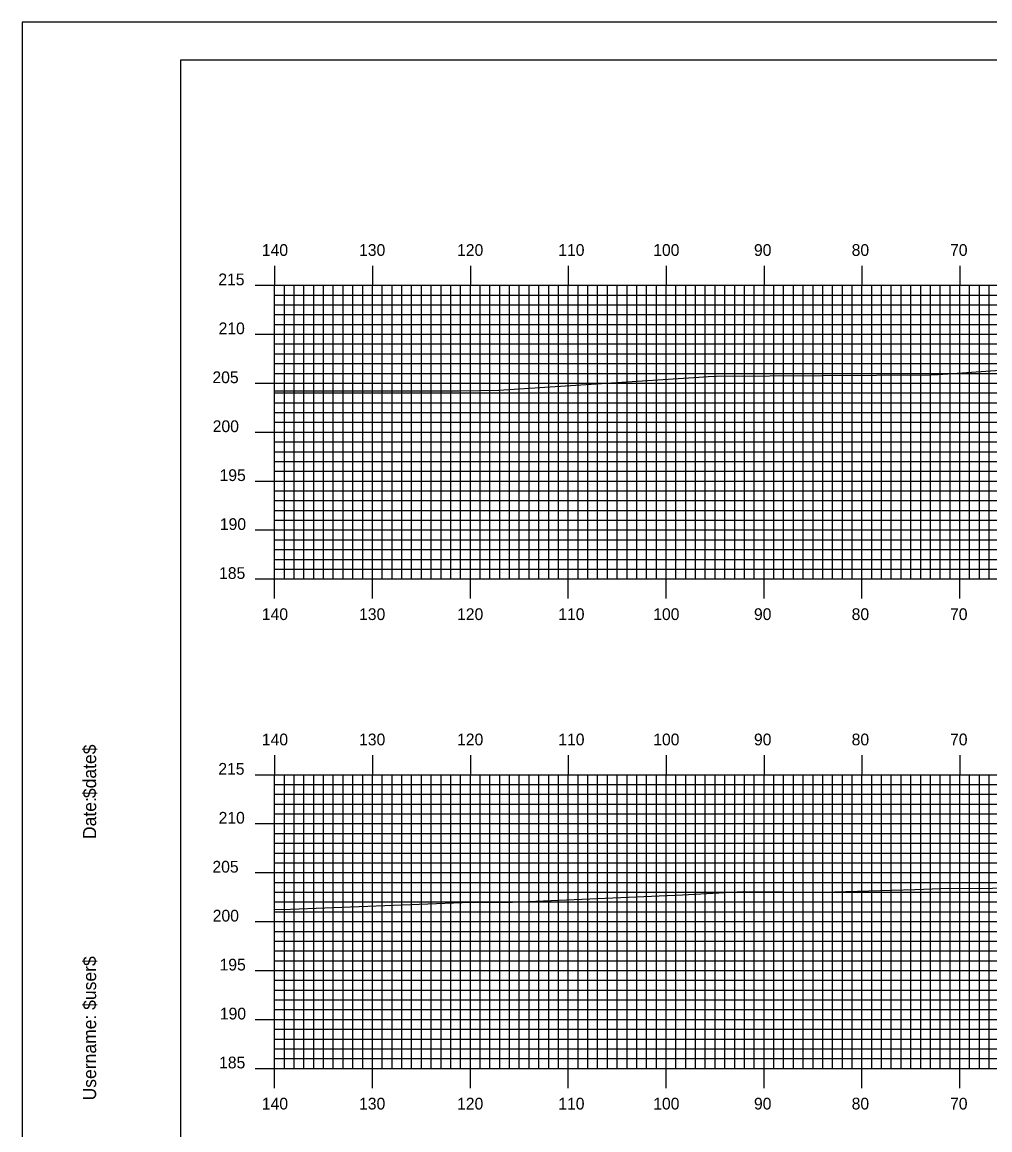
# Model space of a CAD drawing. Extents: x 1799568 to 1799912, y 442591 to 442811.
# Drawn here: x 1799568.2 to 1799667.1, y 442697.4 to 442810.5 of the extents above; entities that cross this region are included whole.
import ezdxf

# ---------------------------------------------------------------- set-up
doc = ezdxf.new("R2010")
doc.units = 0
for name, color, linetype in [('BORDER', 7, 'Continuous'), ('H_V ANNOTATION', 7, 'Continuous'), ('MAJOR', 7, 'Continuous'), ('MINOR', 7, 'Continuous'), ('PLOT BOUNDARY', 7, 'Continuous'), ('S_Roadway_Centerline', 7, 'Continuous')]:
    doc.layers.add(name, color=color, linetype=linetype)

msp = doc.modelspace()

# ---------------------------------------------------------------- linework, layer by layer
at = {"layer": 'BORDER'}
msp.add_lwpolyline([(1799584.41, 442596.67), (1799904.41, 442596.67), (1799904.41, 442806.67), (1799584.41, 442806.67)], close=True, dxfattribs=at)
at = {"layer": 'MAJOR'}
for p, q in [((1799594.01, 442785.67), (1799594.01, 442783.67)), ((1799604.01, 442785.67), (1799604.01, 442783.67)), ((1799614.01, 442785.67), (1799614.01, 442783.67)), ((1799624.01, 442785.67), (1799624.01, 442783.67)), ((1799634.01, 442785.67), (1799634.01, 442783.67)), ((1799644.01, 442785.67), (1799644.01, 442783.67)), ((1799654.01, 442785.67), (1799654.01, 442783.67)), ((1799664.01, 442785.67), (1799664.01, 442783.67)), ((1799592.01, 442783.67), (1799594.01, 442783.67)), ((1799594.01, 442783.67), (1799874.01, 442783.67)), ((1799594.01, 442753.67), (1799594.01, 442783.67)), ((1799594.01, 442753.67), (1799594.01, 442783.67)), ((1799594.01, 442783.67), (1799874.01, 442783.67)), ((1799604.01, 442753.67), (1799604.01, 442783.67)), ((1799614.01, 442753.67), (1799614.01, 442783.67)), ((1799624.01, 442753.67), (1799624.01, 442783.67)), ((1799634.01, 442753.67), (1799634.01, 442783.67)), ((1799644.01, 442753.67), (1799644.01, 442783.67)), ((1799654.01, 442753.67), (1799654.01, 442783.67)), ((1799664.01, 442753.67), (1799664.01, 442783.67)), ((1799592.01, 442778.67), (1799594.01, 442778.67)), ((1799594.01, 442778.67), (1799874.01, 442778.67)), ((1799592.01, 442773.67), (1799594.01, 442773.67)), ((1799594.01, 442773.67), (1799874.01, 442773.67)), ((1799592.01, 442768.67), (1799594.01, 442768.67)), ((1799594.01, 442768.67), (1799874.01, 442768.67)), ((1799592.01, 442763.67), (1799594.01, 442763.67)), ((1799594.01, 442763.67), (1799874.01, 442763.67)), ((1799592.01, 442758.67), (1799594.01, 442758.67)), ((1799594.01, 442758.67), (1799874.01, 442758.67)), ((1799592.01, 442753.67), (1799594.01, 442753.67)), ((1799594.01, 442753.67), (1799874.01, 442753.67)), ((1799594.01, 442753.67), (1799874.01, 442753.67)), ((1799594.01, 442751.66), (1799594.01, 442753.67)), ((1799604.01, 442751.66), (1799604.01, 442753.67)), ((1799614.01, 442751.66), (1799614.01, 442753.67)), ((1799624.01, 442751.66), (1799624.01, 442753.67)), ((1799634.01, 442751.66), (1799634.01, 442753.67)), ((1799644.01, 442751.66), (1799644.01, 442753.67)), ((1799654.01, 442751.66), (1799654.01, 442753.67)), ((1799664.01, 442751.66), (1799664.01, 442753.67)), ((1799594.01, 442735.67), (1799594.01, 442733.67)), ((1799604.01, 442735.67), (1799604.01, 442733.67)), ((1799614.01, 442735.67), (1799614.01, 442733.67)), ((1799624.01, 442735.67), (1799624.01, 442733.67)), ((1799634.01, 442735.67), (1799634.01, 442733.67)), ((1799644.01, 442735.67), (1799644.01, 442733.67)), ((1799654.01, 442735.67), (1799654.01, 442733.67)), ((1799664.01, 442735.67), (1799664.01, 442733.67)), ((1799592.01, 442733.67), (1799594.01, 442733.67)), ((1799594.01, 442733.67), (1799874.01, 442733.67)), ((1799594.01, 442703.67), (1799594.01, 442733.67)), ((1799594.01, 442703.67), (1799594.01, 442733.67)), ((1799594.01, 442733.67), (1799874.01, 442733.67)), ((1799604.01, 442703.67), (1799604.01, 442733.67)), ((1799614.01, 442703.67), (1799614.01, 442733.67)), ((1799624.01, 442703.67), (1799624.01, 442733.67)), ((1799634.01, 442703.67), (1799634.01, 442733.67)), ((1799644.01, 442703.67), (1799644.01, 442733.67)), ((1799654.01, 442703.67), (1799654.01, 442733.67)), ((1799664.01, 442703.67), (1799664.01, 442733.67)), ((1799592.01, 442728.67), (1799594.01, 442728.67)), ((1799594.01, 442728.67), (1799874.01, 442728.67)), ((1799592.01, 442723.67), (1799594.01, 442723.67)), ((1799594.01, 442723.67), (1799874.01, 442723.67)), ((1799592.01, 442718.67), (1799594.01, 442718.67)), ((1799594.01, 442718.67), (1799874.01, 442718.67)), ((1799592.01, 442713.67), (1799594.01, 442713.67)), ((1799594.01, 442713.67), (1799874.01, 442713.67)), ((1799592.01, 442708.67), (1799594.01, 442708.67)), ((1799594.01, 442708.67), (1799874.01, 442708.67)), ((1799592.01, 442703.67), (1799594.01, 442703.67)), ((1799594.01, 442703.67), (1799874.01, 442703.67)), ((1799594.01, 442703.67), (1799874.01, 442703.67)), ((1799594.01, 442701.66), (1799594.01, 442703.67)), ((1799604.01, 442701.66), (1799604.01, 442703.67)), ((1799614.01, 442701.66), (1799614.01, 442703.67)), ((1799624.01, 442701.66), (1799624.01, 442703.67)), ((1799634.01, 442701.66), (1799634.01, 442703.67)), ((1799644.01, 442701.66), (1799644.01, 442703.67)), ((1799654.01, 442701.66), (1799654.01, 442703.67)), ((1799664.01, 442701.66), (1799664.01, 442703.67))]:
    msp.add_line(p, q, dxfattribs=at)
at = {"layer": 'MINOR'}
for p, q in [((1799595.01, 442753.67), (1799595.01, 442783.67)), ((1799596.01, 442753.67), (1799596.01, 442783.67)), ((1799597.01, 442753.67), (1799597.01, 442783.67)), ((1799598.01, 442753.67), (1799598.01, 442783.67)), ((1799599.01, 442753.67), (1799599.01, 442783.67)), ((1799600.01, 442753.67), (1799600.01, 442783.67)), ((1799601.01, 442753.67), (1799601.01, 442783.67)), ((1799602.01, 442753.67), (1799602.01, 442783.67)), ((1799603.01, 442753.67), (1799603.01, 442783.67)), ((1799605.01, 442753.67), (1799605.01, 442783.67)), ((1799606.01, 442753.67), (1799606.01, 442783.67)), ((1799607.01, 442753.67), (1799607.01, 442783.67)), ((1799608.01, 442753.67), (1799608.01, 442783.67)), ((1799609.01, 442753.67), (1799609.01, 442783.67)), ((1799610.01, 442753.67), (1799610.01, 442783.67)), ((1799611.01, 442753.67), (1799611.01, 442783.67)), ((1799612.01, 442753.67), (1799612.01, 442783.67)), ((1799613.01, 442753.67), (1799613.01, 442783.67)), ((1799615.01, 442753.67), (1799615.01, 442783.67)), ((1799616.01, 442753.67), (1799616.01, 442783.67)), ((1799617.01, 442753.67), (1799617.01, 442783.67)), ((1799618.01, 442753.67), (1799618.01, 442783.67)), ((1799619.01, 442753.67), (1799619.01, 442783.67)), ((1799620.01, 442753.67), (1799620.01, 442783.67)), ((1799621.01, 442753.67), (1799621.01, 442783.67)), ((1799622.01, 442753.67), (1799622.01, 442783.67)), ((1799623.01, 442753.67), (1799623.01, 442783.67)), ((1799625.01, 442753.67), (1799625.01, 442783.67)), ((1799626.01, 442753.67), (1799626.01, 442783.67)), ((1799627.01, 442753.67), (1799627.01, 442783.67)), ((1799628.01, 442753.67), (1799628.01, 442783.67)), ((1799629.01, 442753.67), (1799629.01, 442783.67)), ((1799630.01, 442753.67), (1799630.01, 442783.67)), ((1799631.01, 442753.67), (1799631.01, 442783.67)), ((1799632.01, 442753.67), (1799632.01, 442783.67)), ((1799633.01, 442753.67), (1799633.01, 442783.67)), ((1799635.01, 442753.67), (1799635.01, 442783.67)), ((1799636.01, 442753.67), (1799636.01, 442783.67)), ((1799637.01, 442753.67), (1799637.01, 442783.67)), ((1799638.01, 442753.67), (1799638.01, 442783.67)), ((1799639.01, 442753.67), (1799639.01, 442783.67)), ((1799640.01, 442753.67), (1799640.01, 442783.67)), ((1799641.01, 442753.67), (1799641.01, 442783.67)), ((1799642.01, 442753.67), (1799642.01, 442783.67)), ((1799643.01, 442753.67), (1799643.01, 442783.67)), ((1799645.01, 442753.67), (1799645.01, 442783.67)), ((1799646.01, 442753.67), (1799646.01, 442783.67)), ((1799647.01, 442753.67), (1799647.01, 442783.67)), ((1799648.01, 442753.67), (1799648.01, 442783.67)), ((1799649.01, 442753.67), (1799649.01, 442783.67)), ((1799650.01, 442753.67), (1799650.01, 442783.67)), ((1799651.01, 442753.67), (1799651.01, 442783.67)), ((1799652.01, 442753.67), (1799652.01, 442783.67)), ((1799653.01, 442753.67), (1799653.01, 442783.67)), ((1799655.01, 442753.67), (1799655.01, 442783.67)), ((1799656.01, 442753.67), (1799656.01, 442783.67)), ((1799657.01, 442753.67), (1799657.01, 442783.67)), ((1799658.01, 442753.67), (1799658.01, 442783.67)), ((1799659.01, 442753.67), (1799659.01, 442783.67)), ((1799660.01, 442753.67), (1799660.01, 442783.67)), ((1799661.01, 442753.67), (1799661.01, 442783.67)), ((1799662.01, 442753.67), (1799662.01, 442783.67)), ((1799663.01, 442753.67), (1799663.01, 442783.67)), ((1799665.01, 442753.67), (1799665.01, 442783.67)), ((1799666.01, 442753.67), (1799666.01, 442783.67)), ((1799667.01, 442753.67), (1799667.01, 442783.67)), ((1799594.01, 442782.67), (1799874.01, 442782.67)), ((1799594.01, 442782.67), (1799596.01, 442782.67)), ((1799594.01, 442781.67), (1799874.01, 442781.67)), ((1799594.01, 442781.67), (1799596.01, 442781.67)), ((1799594.01, 442780.67), (1799874.01, 442780.67)), ((1799594.01, 442780.67), (1799596.01, 442780.67)), ((1799594.01, 442779.67), (1799874.01, 442779.67)), ((1799594.01, 442779.67), (1799596.01, 442779.67)), ((1799594.01, 442777.67), (1799874.01, 442777.67)), ((1799594.01, 442777.67), (1799596.01, 442777.67)), ((1799594.01, 442776.67), (1799874.01, 442776.67)), ((1799594.01, 442776.67), (1799596.01, 442776.67)), ((1799594.01, 442775.67), (1799874.01, 442775.67)), ((1799594.01, 442775.67), (1799596.01, 442775.67)), ((1799594.01, 442774.67), (1799874.01, 442774.67)), ((1799594.01, 442774.67), (1799596.01, 442774.67)), ((1799594.01, 442772.67), (1799874.01, 442772.67)), ((1799594.01, 442772.67), (1799596.01, 442772.67)), ((1799594.01, 442771.67), (1799874.01, 442771.67)), ((1799594.01, 442771.67), (1799596.01, 442771.67)), ((1799594.01, 442770.67), (1799874.01, 442770.67)), ((1799594.01, 442770.67), (1799596.01, 442770.67)), ((1799594.01, 442769.67), (1799874.01, 442769.67)), ((1799594.01, 442769.67), (1799596.01, 442769.67)), ((1799594.01, 442767.67), (1799874.01, 442767.67)), ((1799594.01, 442767.67), (1799596.01, 442767.67)), ((1799594.01, 442766.67), (1799874.01, 442766.67)), ((1799594.01, 442766.67), (1799596.01, 442766.67)), ((1799594.01, 442765.67), (1799874.01, 442765.67)), ((1799594.01, 442765.67), (1799596.01, 442765.67)), ((1799594.01, 442764.67), (1799874.01, 442764.67)), ((1799594.01, 442764.67), (1799596.01, 442764.67)), ((1799594.01, 442762.67), (1799874.01, 442762.67)), ((1799594.01, 442762.67), (1799596.01, 442762.67)), ((1799594.01, 442761.67), (1799874.01, 442761.67)), ((1799594.01, 442761.67), (1799596.01, 442761.67)), ((1799594.01, 442760.67), (1799874.01, 442760.67)), ((1799594.01, 442760.67), (1799596.01, 442760.67)), ((1799594.01, 442759.67), (1799874.01, 442759.67)), ((1799594.01, 442759.67), (1799596.01, 442759.67)), ((1799594.01, 442757.67), (1799874.01, 442757.67)), ((1799594.01, 442757.67), (1799596.01, 442757.67)), ((1799594.01, 442756.67), (1799874.01, 442756.67)), ((1799594.01, 442756.67), (1799596.01, 442756.67)), ((1799594.01, 442755.67), (1799874.01, 442755.67)), ((1799594.01, 442755.67), (1799596.01, 442755.67)), ((1799594.01, 442754.67), (1799874.01, 442754.67)), ((1799594.01, 442754.67), (1799596.01, 442754.67)), ((1799595.01, 442703.67), (1799595.01, 442733.67)), ((1799596.01, 442703.67), (1799596.01, 442733.67)), ((1799597.01, 442703.67), (1799597.01, 442733.67)), ((1799598.01, 442703.67), (1799598.01, 442733.67)), ((1799599.01, 442703.67), (1799599.01, 442733.67)), ((1799600.01, 442703.67), (1799600.01, 442733.67)), ((1799601.01, 442703.67), (1799601.01, 442733.67)), ((1799602.01, 442703.67), (1799602.01, 442733.67)), ((1799603.01, 442703.67), (1799603.01, 442733.67)), ((1799605.01, 442703.67), (1799605.01, 442733.67)), ((1799606.01, 442703.67), (1799606.01, 442733.67)), ((1799607.01, 442703.67), (1799607.01, 442733.67)), ((1799608.01, 442703.67), (1799608.01, 442733.67)), ((1799609.01, 442703.67), (1799609.01, 442733.67)), ((1799610.01, 442703.67), (1799610.01, 442733.67)), ((1799611.01, 442703.67), (1799611.01, 442733.67)), ((1799612.01, 442703.67), (1799612.01, 442733.67)), ((1799613.01, 442703.67), (1799613.01, 442733.67)), ((1799615.01, 442703.67), (1799615.01, 442733.67)), ((1799616.01, 442703.67), (1799616.01, 442733.67)), ((1799617.01, 442703.67), (1799617.01, 442733.67)), ((1799618.01, 442703.67), (1799618.01, 442733.67)), ((1799619.01, 442703.67), (1799619.01, 442733.67)), ((1799620.01, 442703.67), (1799620.01, 442733.67)), ((1799621.01, 442703.67), (1799621.01, 442733.67)), ((1799622.01, 442703.67), (1799622.01, 442733.67)), ((1799623.01, 442703.67), (1799623.01, 442733.67)), ((1799625.01, 442703.67), (1799625.01, 442733.67)), ((1799626.01, 442703.67), (1799626.01, 442733.67)), ((1799627.01, 442703.67), (1799627.01, 442733.67)), ((1799628.01, 442703.67), (1799628.01, 442733.67)), ((1799629.01, 442703.67), (1799629.01, 442733.67)), ((1799630.01, 442703.67), (1799630.01, 442733.67)), ((1799631.01, 442703.67), (1799631.01, 442733.67)), ((1799632.01, 442703.67), (1799632.01, 442733.67)), ((1799633.01, 442703.67), (1799633.01, 442733.67)), ((1799635.01, 442703.67), (1799635.01, 442733.67)), ((1799636.01, 442703.67), (1799636.01, 442733.67)), ((1799637.01, 442703.67), (1799637.01, 442733.67)), ((1799638.01, 442703.67), (1799638.01, 442733.67)), ((1799639.01, 442703.67), (1799639.01, 442733.67)), ((1799640.01, 442703.67), (1799640.01, 442733.67)), ((1799641.01, 442703.67), (1799641.01, 442733.67)), ((1799642.01, 442703.67), (1799642.01, 442733.67)), ((1799643.01, 442703.67), (1799643.01, 442733.67)), ((1799645.01, 442703.67), (1799645.01, 442733.67)), ((1799646.01, 442703.67), (1799646.01, 442733.67)), ((1799647.01, 442703.67), (1799647.01, 442733.67)), ((1799648.01, 442703.67), (1799648.01, 442733.67)), ((1799649.01, 442703.67), (1799649.01, 442733.67)), ((1799650.01, 442703.67), (1799650.01, 442733.67)), ((1799651.01, 442703.67), (1799651.01, 442733.67)), ((1799652.01, 442703.67), (1799652.01, 442733.67)), ((1799653.01, 442703.67), (1799653.01, 442733.67)), ((1799655.01, 442703.67), (1799655.01, 442733.67)), ((1799656.01, 442703.67), (1799656.01, 442733.67)), ((1799657.01, 442703.67), (1799657.01, 442733.67)), ((1799658.01, 442703.67), (1799658.01, 442733.67)), ((1799659.01, 442703.67), (1799659.01, 442733.67)), ((1799660.01, 442703.67), (1799660.01, 442733.67)), ((1799661.01, 442703.67), (1799661.01, 442733.67)), ((1799662.01, 442703.67), (1799662.01, 442733.67)), ((1799663.01, 442703.67), (1799663.01, 442733.67)), ((1799665.01, 442703.67), (1799665.01, 442733.67)), ((1799666.01, 442703.67), (1799666.01, 442733.67)), ((1799667.01, 442703.67), (1799667.01, 442733.67)), ((1799594.01, 442732.67), (1799874.01, 442732.67)), ((1799594.01, 442732.67), (1799596.01, 442732.67)), ((1799594.01, 442731.67), (1799874.01, 442731.67)), ((1799594.01, 442731.67), (1799596.01, 442731.67)), ((1799594.01, 442730.67), (1799874.01, 442730.67)), ((1799594.01, 442730.67), (1799596.01, 442730.67)), ((1799594.01, 442729.67), (1799874.01, 442729.67)), ((1799594.01, 442729.67), (1799596.01, 442729.67)), ((1799594.01, 442727.67), (1799874.01, 442727.67)), ((1799594.01, 442727.67), (1799596.01, 442727.67)), ((1799594.01, 442726.67), (1799874.01, 442726.67)), ((1799594.01, 442726.67), (1799596.01, 442726.67)), ((1799594.01, 442725.67), (1799874.01, 442725.67)), ((1799594.01, 442725.67), (1799596.01, 442725.67)), ((1799594.01, 442724.67), (1799874.01, 442724.67)), ((1799594.01, 442724.67), (1799596.01, 442724.67)), ((1799594.01, 442722.67), (1799874.01, 442722.67)), ((1799594.01, 442722.67), (1799596.01, 442722.67)), ((1799594.01, 442721.67), (1799874.01, 442721.67)), ((1799594.01, 442721.67), (1799596.01, 442721.67)), ((1799594.01, 442720.67), (1799874.01, 442720.67)), ((1799594.01, 442720.67), (1799596.01, 442720.67)), ((1799594.01, 442719.67), (1799874.01, 442719.67)), ((1799594.01, 442719.67), (1799596.01, 442719.67)), ((1799594.01, 442717.67), (1799874.01, 442717.67)), ((1799594.01, 442717.67), (1799596.01, 442717.67)), ((1799594.01, 442716.67), (1799874.01, 442716.67)), ((1799594.01, 442716.67), (1799596.01, 442716.67)), ((1799594.01, 442715.67), (1799874.01, 442715.67)), ((1799594.01, 442715.67), (1799596.01, 442715.67)), ((1799594.01, 442714.67), (1799874.01, 442714.67)), ((1799594.01, 442714.67), (1799596.01, 442714.67)), ((1799594.01, 442712.67), (1799874.01, 442712.67)), ((1799594.01, 442712.67), (1799596.01, 442712.67)), ((1799594.01, 442711.67), (1799874.01, 442711.67)), ((1799594.01, 442711.67), (1799596.01, 442711.67)), ((1799594.01, 442710.67), (1799874.01, 442710.67)), ((1799594.01, 442710.67), (1799596.01, 442710.67)), ((1799594.01, 442709.67), (1799874.01, 442709.67)), ((1799594.01, 442709.67), (1799596.01, 442709.67)), ((1799594.01, 442707.67), (1799874.01, 442707.67)), ((1799594.01, 442707.67), (1799596.01, 442707.67)), ((1799594.01, 442706.67), (1799874.01, 442706.67)), ((1799594.01, 442706.67), (1799596.01, 442706.67)), ((1799594.01, 442705.67), (1799874.01, 442705.67)), ((1799594.01, 442705.67), (1799596.01, 442705.67)), ((1799594.01, 442704.67), (1799874.01, 442704.67)), ((1799594.01, 442704.67), (1799596.01, 442704.67))]:
    msp.add_line(p, q, dxfattribs=at)
at = {"layer": 'PLOT BOUNDARY'}
msp.add_lwpolyline([(1799568.22, 442590.55), (1799908.22, 442590.55), (1799908.22, 442810.55), (1799568.22, 442810.55)], close=True, dxfattribs=at)
at = {"layer": 'S_Roadway_Centerline'}
for points in [[(1799594.01, 442772.87), (1799612.88, 442772.89), (1799616.92, 442772.95), (1799637.36, 442774.28), (1799638.29, 442774.36), (1799639.12, 442774.38), (1799660.98, 442774.53), (1799661.78, 442774.57), (1799673.01, 442775.34), (1799678.53, 442775.5), (1799695.85, 442775.53), (1799707.37, 442775.82), (1799709.4, 442775.86), (1799732.2, 442776.5), (1799733.54, 442776.55), (1799743.03, 442776.75), (1799756.05, 442777.02), (1799765.34, 442777.04), (1799776.04, 442777.28), (1799778.11, 442777.28), (1799780.07, 442777.19), (1799788.87, 442776.77), (1799799.24, 442777.09)], [(1799594.01, 442719.89), (1799595.64, 442719.95), (1799613.16, 442720.63), (1799618.33, 442720.65), (1799635.69, 442721.39), (1799641.86, 442721.73), (1799650.01, 442721.67), (1799659.41, 442721.95), (1799662.94, 442722.07), (1799666.11, 442722.03), (1799681, 442722.46), (1799689.09, 442722.87), (1799697.17, 442723.13), (1799714.49, 442723.04), (1799726.1, 442723.39), (1799731.09, 442723.58), (1799750.91, 442724.04), (1799755.54, 442724.14), (1799760.22, 442724.12), (1799773.17, 442724.3), (1799784.95, 442724.59), (1799790.22, 442724.67), (1799809.27, 442725.24)]]:
    msp.add_lwpolyline(points, dxfattribs=at)

# ---------------------------------------------------------------- texts
at = {"layer": 'BORDER'}
for s, p in [('$date$', (1799575.78, 442731.28)), ('Date:', (1799575.78, 442727.1)), ('$user$', (1799575.78, 442709.65)), ('Username:', (1799575.78, 442700.4))]:
    msp.add_text(s, height=1.339, rotation=90, dxfattribs=at).set_placement(p)
at = {"layer": 'H_V ANNOTATION'}
for s, p in [('140', (1799592.71, 442786.67)), ('130', (1799602.64, 442786.67)), ('120', (1799612.65, 442786.67)), ('110', (1799622.99, 442786.67)), ('100', (1799632.69, 442786.67)), ('90', (1799642.98, 442786.67)), ('80', (1799652.96, 442786.67)), ('70', (1799663.01, 442786.67)), ('215', (1799588.26, 442783.67)), ('210', (1799588.29, 442778.67)), ('205', (1799587.66, 442773.67)), ('200', (1799587.69, 442768.67)), ('195', (1799588.39, 442763.67)), ('190', (1799588.42, 442758.67)), ('185', (1799588.34, 442753.67)), ('140', (1799592.71, 442749.47)), ('130', (1799602.64, 442749.47)), ('120', (1799612.65, 442749.47)), ('110', (1799622.99, 442749.47)), ('100', (1799632.69, 442749.47)), ('90', (1799642.98, 442749.47)), ('80', (1799652.96, 442749.47)), ('70', (1799663.01, 442749.47)), ('140', (1799592.71, 442736.67)), ('130', (1799602.64, 442736.67)), ('120', (1799612.65, 442736.67)), ('110', (1799622.99, 442736.67)), ('100', (1799632.69, 442736.67)), ('90', (1799642.98, 442736.67)), ('80', (1799652.96, 442736.67)), ('70', (1799663.01, 442736.67)), ('215', (1799588.26, 442733.67)), ('210', (1799588.29, 442728.67)), ('205', (1799587.66, 442723.67)), ('200', (1799587.69, 442718.67)), ('195', (1799588.39, 442713.67)), ('190', (1799588.42, 442708.67)), ('185', (1799588.34, 442703.67)), ('140', (1799592.71, 442699.47)), ('130', (1799602.64, 442699.47)), ('120', (1799612.65, 442699.47)), ('110', (1799622.99, 442699.47)), ('100', (1799632.69, 442699.47)), ('90', (1799642.98, 442699.47)), ('80', (1799652.96, 442699.47)), ('70', (1799663.01, 442699.47))]:
    msp.add_text(s, height=1.2, dxfattribs=at).set_placement(p)
at = {"layer": 'MAJOR'}
for p in [(1799594, 442753.67), (1799594, 442703.67)]:
    msp.add_text('-', height=0.012, dxfattribs=at).set_placement(p)

doc.saveas('drawing.dxf')
